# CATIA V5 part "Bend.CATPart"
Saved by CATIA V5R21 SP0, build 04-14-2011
Part number: Bend
Bounding box of the stored display mesh (mm): x -50 to 50, y -150 to 15, z -50 to 115
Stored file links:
  D:\CATIA V5R21 E-RESOURCES\CATIA-V5R21\catia-v5r21-Prts\c12_catia_v5r21_prt\c12_catia_v5r21figr_12-44\Bend.CATPart
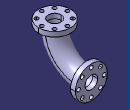
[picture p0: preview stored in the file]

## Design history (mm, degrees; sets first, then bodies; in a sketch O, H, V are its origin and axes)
Body1 (main body)
  Sketch1 on yz-plane, origin (0, 0, 0), H (0, 1, 0), V (0, 0, 1)
    arc A1 centre (0, 100) radius 100 from (-100, 100) to (0, 0) ccw
    point P1 (0, 100)
    coincidence: P1 V
  Sketch2 on zx-plane, origin (0, 0, 0), H (-1, 0, 0), V (0, 0, 1)
    circle A1 centre (0, 0) radius 30
    point P1 (0, -30)
    radius A1 = 30
    coincidence: A1 P1, P1 V
  Rib1: profile Sketch2, centre curve Sketch1
  Sketch3 on face of Rib1, origin (0, 0, 0), H (-1, 0, 0), V (0, 0, 1)
    circle A1 centre (0, 0) radius 50
    point P1 (0, -50)
    radius A1 = 50
    coincidence: A1 P1, P1 V
  Pad1: profile Sketch3, direction (0, 1, 0), length 15
  Sketch4 on face of Rib1, origin (0, 0, 100), H (1, 0, 0), V (0, 1, 0)
    circle A1 centre (0, -100) radius 50
    point P1 (0, -100)
    reference projected circle E1 centre (0, -100) radius 30 from edge [face of Rib1 | face of Rib1]
    radius A1 = 50
    coincidence: P1 V
    concentricity: A1 E1
  Pad2: profile Sketch4, direction (0, 0, 1), length 15
  Sketch5 on face of Pad1, origin (0, 15, 0), H (-1, 0, 0), V (0, 0, 1)
    circle A1 centre (0, 0) radius 20
    radius A1 = 20
  Sketch6 on yz-plane, origin (0, 0, 0), H (0, 1, 0), V (0, 0, 1)
    projected arc E1 centre (0, 100) radius 100 from (-100, 100) to (0, 0) ccw from edge of Sketch1
    line L1 (-100, 100) -> (-100, 115)
    point P3 (-100, 115)
    line L2 (0, 0) -> (15, 0)
    point P4 (15, 0)
    reference projected line E2 (15, 50) -> (15, -50) from edge [face of Pad1 | face of Pad1]
    reference projected line E3 (-50, 115) -> (-150, 115) from edge [face of Pad2 | face of Pad2]
    tangency: L1 E1, L2 E1
    coincidence: P4 E2, P3 E3
  Slot1: profile Sketch5, centre curve Sketch6
  Sketch7 on face of Pad1, origin (0, 15, 0), H (-1, 0, 0), V (0, 0, 1)
    circle A1 centre (0, -40) radius 6
    point P1 (0, -40)
    radius A1 = 6
    distance H P1 = 40
    coincidence: P1 V
  Pocket1: profile Sketch7, direction (0, -1, 0), length 15
  CircPattern1: of Pocket1, instances 8, angular step 45, axis from face of Pad1
  Sketch8 on face of Pad2, origin (0, 0, 115), H (1, 0, 0), V (0, 1, 0)
    circle A1 centre (0, -140) radius 6
    point P1 (0, -140)
    reference projected point E1 (0, -100) from vertex of Sketch1
    radius A1 = 6
    distance E1 P1 = 40
    coincidence: P1 V
  Pocket2: profile Sketch8, direction (0, 0, -1), length 15
  CircPattern2: of Pocket2, instances 8, angular step 45, axis from face of Pad2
